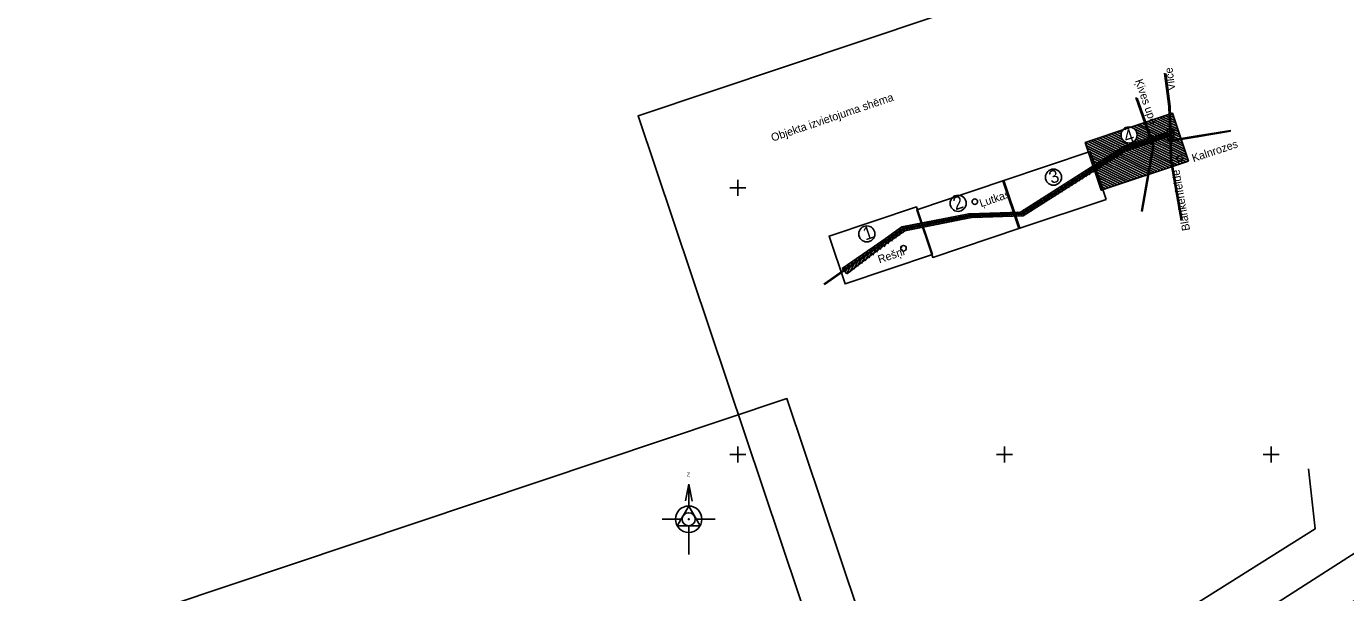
# Model space of a CAD drawing. Extents: x 469981 to 472086, y 246785 to 247785.
# Drawn here: x 471366.7 to 471613.9, y 247524.1 to 247630.3 of the extents above; entities that cross this region are included whole.
import ezdxf

# ---------------------------------------------------------------- set-up
doc = ezdxf.new("R2010")
doc.units = 0
for name, color, linetype in [('DREN_VADP_####_####_#', 7, 'Continuous'), ('GEOD_ELEM_####_####_#', 7, 'Continuous'), ('RAMI_PLAN_####_TKST_#', 7, 'Continuous'), ('RAMI_UZMR_####_####_#', 7, 'Continuous'), ('RELJ_NOGA_####_####_#', 7, 'Continuous'), ('RELJ_NOGL_####_####_#', 7, 'Continuous')]:
    doc.layers.add(name, color=color, linetype=linetype)

msp = doc.modelspace()

# ---------------------------------------------------------------- linework, layer by layer
at = {"layer": 'DREN_VADP_####_####_#'}
msp.add_lwpolyline([(471456.42, 247440.55), (471608.21, 247536.04), (471607, 247547.3)], dxfattribs=at)
at = {"layer": 'GEOD_ELEM_####_####_#'}
for p, q in [((471498.5, 247600), (471500, 247600)), ((471500, 247601.5), (471500, 247600)), ((471500, 247600), (471500, 247598.5)), ((471500, 247600), (471501.5, 247600)), ((471500, 247551.5), (471500, 247550)), ((471550, 247551.5), (471550, 247550)), ((471600, 247551.5), (471600, 247550)), ((471498.5, 247550), (471500, 247550)), ((471500, 247550), (471500, 247548.5)), ((471500, 247550), (471501.5, 247550)), ((471548.5, 247550), (471550, 247550)), ((471550, 247550), (471550, 247548.5)), ((471550, 247550), (471551.5, 247550)), ((471598.5, 247550), (471600, 247550)), ((471600, 247550), (471600, 247548.5)), ((471600, 247550), (471601.5, 247550))]:
    msp.add_line(p, q, dxfattribs=at)
at = {"layer": 'RAMI_PLAN_####_TKST_#'}
for p, q in [((471583.56, 247607.82), (471575.33, 247611.91)), ((471583.38, 247608.35), (471575.87, 247612.09)), ((471583.2, 247608.89), (471576.4, 247612.27)), ((471583.02, 247609.43), (471576.94, 247612.45)), ((471582.84, 247609.96), (471577.48, 247612.63)), ((471582.66, 247610.5), (471578.01, 247612.81)), ((471582.48, 247611.03), (471578.55, 247612.99)), ((471582.3, 247611.57), (471579.08, 247613.17)), ((471582.12, 247612.11), (471579.62, 247613.35)), ((471581.94, 247612.64), (471580.16, 247613.53)), ((471581.76, 247613.18), (471580.69, 247613.71)), ((471581.58, 247613.72), (471581.23, 247613.89)), ((471579.77, 247603.45), (471567.82, 247609.4)), ((471580.31, 247603.63), (471568.36, 247609.58)), ((471580.84, 247603.81), (471568.89, 247609.76)), ((471581.38, 247603.99), (471569.43, 247609.94)), ((471572.2, 247609.01), (471569.97, 247610.12)), ((471571.95, 247609.58), (471570.5, 247610.3)), ((471571.95, 247610.02), (471571.04, 247610.48)), ((471571.99, 247610.45), (471571.58, 247610.66)), ((471572.3, 247610.74), (471572.11, 247610.83)), ((471572.78, 247610.95), (471572.65, 247611.01)), ((471573.36, 247611.11), (471573.18, 247611.19)), ((471584.1, 247606.21), (471573.72, 247611.37)), ((471583.92, 247606.74), (471574.26, 247611.55)), ((471584.28, 247605.67), (471574.71, 247610.43)), ((471583.74, 247607.28), (471574.79, 247611.73)), ((471584.46, 247605.13), (471574.84, 247609.93)), ((471584.06, 247604.88), (471574.88, 247609.46)), ((471576.71, 247608.1), (471577.35, 247609.38)), ((471576.83, 247609.69), (471577.45, 247609.32)), ((471577.25, 247608.28), (471577.89, 247609.56)), ((471577.45, 247609.32), (471577.6, 247609.81)), ((471577.79, 247608.46), (471578.43, 247609.74)), ((471578.32, 247608.64), (471578.96, 247609.92)), ((471578.86, 247608.82), (471579.5, 247610.1)), ((471579.4, 247609), (471580.04, 247610.28)), ((471579.93, 247609.17), (471580.57, 247610.46)), ((471580.47, 247609.35), (471581.11, 247610.64)), ((471580.52, 247610.96), (471581.73, 247610.97)), ((471580.53, 247610.47), (471580.52, 247610.96)), ((471580.59, 247608.73), (471580.58, 247609.61)), ((471580.72, 247608.96), (471581.64, 247610.82)), ((471581.11, 247608.84), (471581.75, 247610.14)), ((471581.73, 247610.97), (471581.75, 247608.74)), ((471577.09, 247602.55), (471565.14, 247608.5)), ((471576.55, 247602.37), (471565.32, 247607.96)), ((471576.02, 247602.19), (471565.5, 247607.43)), ((471577.63, 247602.73), (471565.68, 247608.68)), ((471575.48, 247602.01), (471565.68, 247606.89)), ((471578.16, 247602.91), (471566.21, 247608.86)), ((471578.7, 247603.09), (471566.75, 247609.04)), ((471579.24, 247603.27), (471567.28, 247609.22)), ((471570.4, 247605.28), (471571.25, 247607)), ((471571.05, 247605.69), (471571.9, 247607.41)), ((471571.69, 247606.09), (471572.53, 247607.76)), ((471572.34, 247606.49), (471573.06, 247607.94)), ((471572.96, 247606.84), (471573.6, 247608.12)), ((471581.92, 247604.17), (471573.3, 247608.45)), ((471573.5, 247607.02), (471574.14, 247608.3)), ((471582.45, 247604.35), (471574.01, 247608.55)), ((471574.03, 247607.2), (471574.67, 247608.48)), ((471582.99, 247604.53), (471574.38, 247608.81)), ((471574.57, 247607.38), (471575.21, 247608.66)), ((471583.53, 247604.7), (471574.6, 247609.15)), ((471575.1, 247607.56), (471575.74, 247608.84)), ((471575.64, 247607.74), (471576.28, 247609.02)), ((471576.18, 247607.92), (471576.82, 247609.2)), ((471577.31, 247608.34), (471577.57, 247608.82)), ((471577.57, 247608.82), (471578.05, 247608.57)), ((471581.75, 247608.74), (471580.59, 247608.73)), ((471581.52, 247608.77), (471581.76, 247609.25)), ((471574.94, 247601.83), (471565.86, 247606.35)), ((471574.41, 247601.65), (471566.04, 247605.82)), ((471573.87, 247601.47), (471566.22, 247605.28)), ((471573.34, 247601.29), (471566.4, 247604.74)), ((471566.51, 247602.86), (471567.35, 247604.54)), ((471567.16, 247603.26), (471568, 247604.95)), ((471567.81, 247603.67), (471568.65, 247605.36)), ((471568.45, 247604.07), (471569.3, 247605.77)), ((471569.1, 247604.47), (471569.95, 247606.18)), ((471569.75, 247604.88), (471570.6, 247606.59)), ((471562.62, 247600.43), (471563.44, 247602.08)), ((471563.27, 247600.84), (471564.09, 247602.49)), ((471563.92, 247601.24), (471564.74, 247602.9)), ((471564.57, 247601.65), (471565.39, 247603.31)), ((471565.21, 247602.05), (471566.04, 247603.72)), ((471565.86, 247602.45), (471566.69, 247604.13)), ((471572.8, 247601.11), (471566.58, 247604.21)), ((471572.26, 247600.93), (471566.76, 247603.67)), ((471571.73, 247600.75), (471566.94, 247603.13)), ((471571.19, 247600.57), (471567.12, 247602.6)), ((471570.65, 247600.39), (471567.3, 247602.06)), ((471558.73, 247598.01), (471559.53, 247599.62)), ((471559.38, 247598.41), (471560.19, 247600.03)), ((471560.03, 247598.82), (471560.84, 247600.44)), ((471560.68, 247599.22), (471561.49, 247600.85)), ((471561.33, 247599.63), (471562.14, 247601.26)), ((471561.97, 247600.03), (471562.79, 247601.67)), ((471570.12, 247600.21), (471567.48, 247601.53)), ((471569.58, 247600.03), (471567.66, 247600.99)), ((471569.04, 247599.85), (471567.84, 247600.45)), ((471568.51, 247599.67), (471568.02, 247599.92)), ((471554.85, 247595.59), (471555.63, 247597.16)), ((471555.49, 247595.99), (471556.28, 247597.57)), ((471556.14, 247596.39), (471556.93, 247597.98)), ((471556.79, 247596.8), (471557.58, 247598.39)), ((471557.44, 247597.2), (471558.23, 247598.8)), ((471558.09, 247597.61), (471558.88, 247599.21)), ((471540.03, 247593.65), (471540.49, 247594.58)), ((471540.53, 247593.75), (471540.99, 247594.67)), ((471541.02, 247593.85), (471541.48, 247594.77)), ((471541.52, 247593.94), (471541.98, 247594.87)), ((471542.01, 247594.04), (471542.47, 247594.97)), ((471542.51, 247594.14), (471542.97, 247595.06)), ((471543, 247594.24), (471543.45, 247595.14)), ((471543.5, 247594.33), (471543.91, 247595.15)), ((471543.96, 247594.37), (471544.36, 247595.17)), ((471544.42, 247594.39), (471544.82, 247595.19)), ((471544.88, 247594.41), (471545.27, 247595.21)), ((471545.33, 247594.43), (471545.73, 247595.22)), ((471545.79, 247594.45), (471546.18, 247595.24)), ((471546.25, 247594.47), (471546.64, 247595.26)), ((471546.7, 247594.49), (471547.09, 247595.27)), ((471547.16, 247594.51), (471547.55, 247595.29)), ((471547.62, 247594.53), (471548, 247595.31)), ((471548.07, 247594.55), (471548.46, 247595.32)), ((471548.53, 247594.57), (471548.92, 247595.34)), ((471548.99, 247594.59), (471549.37, 247595.36)), ((471549.44, 247594.61), (471549.83, 247595.38)), ((471549.9, 247594.63), (471550.28, 247595.39)), ((471550.36, 247594.65), (471550.74, 247595.41)), ((471550.81, 247594.67), (471551.19, 247595.43)), ((471551.27, 247594.69), (471551.65, 247595.44)), ((471551.73, 247594.71), (471552.1, 247595.46)), ((471552.18, 247594.73), (471552.56, 247595.48)), ((471552.64, 247594.75), (471553.02, 247595.52)), ((471553.1, 247594.77), (471553.68, 247595.93)), ((471553.56, 247594.79), (471554.33, 247596.34)), ((471554.2, 247595.18), (471554.98, 247596.75)), ((471528.84, 247590.02), (471529.85, 247592.05)), ((471529.55, 247590.54), (471530.53, 247592.52)), ((471530.25, 247591.07), (471531.08, 247592.73)), ((471530.96, 247591.59), (471531.58, 247592.83)), ((471531.61, 247592), (471532.07, 247592.92)), ((471532.11, 247592.09), (471532.57, 247593.02)), ((471532.6, 247592.19), (471533.06, 247593.12)), ((471533.1, 247592.29), (471533.56, 247593.22)), ((471533.59, 247592.39), (471534.05, 247593.31)), ((471534.09, 247592.48), (471534.55, 247593.41)), ((471534.58, 247592.58), (471535.04, 247593.51)), ((471535.08, 247592.68), (471535.54, 247593.6)), ((471535.57, 247592.77), (471536.03, 247593.7)), ((471536.07, 247592.87), (471536.53, 247593.8)), ((471536.56, 247592.97), (471537.02, 247593.9)), ((471537.06, 247593.07), (471537.52, 247593.99)), ((471537.55, 247593.16), (471538.02, 247594.09)), ((471538.05, 247593.26), (471538.51, 247594.19)), ((471538.54, 247593.36), (471539.01, 247594.29)), ((471539.04, 247593.46), (471539.5, 247594.38)), ((471539.54, 247593.55), (471540, 247594.48)), ((471525.3, 247587.39), (471526.42, 247589.66)), ((471526.01, 247587.92), (471527.11, 247590.14)), ((471526.71, 247588.44), (471527.79, 247590.61)), ((471527.42, 247588.97), (471528.48, 247591.09)), ((471528.13, 247589.49), (471529.16, 247591.57)), ((471521.76, 247584.77), (471523, 247587.27)), ((471522.47, 247585.3), (471523.69, 247587.75)), ((471523.17, 247585.82), (471524.37, 247588.23)), ((471523.88, 247586.35), (471525.06, 247588.7)), ((471524.59, 247586.87), (471525.74, 247589.18)), ((471519.58, 247584.88), (471520.47, 247583.89)), ((471519.87, 247584.56), (471520.26, 247585.36)), ((471520.15, 247584.25), (471520.95, 247585.84)), ((471520.44, 247583.93), (471521.63, 247586.32)), ((471521.05, 247584.25), (471522.32, 247586.79)), ((471490.19, 247541.3), (471490.81, 247544.46)), ((471490.81, 247544.46), (471491.44, 247541.26)), ((471490.81, 247544.46), (471490.81, 247540.34)), ((471490.81, 247540.34), (471488.67, 247536.63)), ((471490.81, 247541.16), (471490.81, 247541)), ((471490.81, 247541), (471490.81, 247541.16)), ((471490.81, 247541.16), (471490.81, 247541)), ((471490.81, 247540.34), (471492.95, 247536.63)), ((471489.38, 247537.86), (471485.86, 247537.86)), ((471495.76, 247537.86), (471492.23, 247537.86)), ((471492.95, 247536.63), (471488.67, 247536.63)), ((471490.81, 247536.63), (471490.81, 247531.26))]:
    msp.add_line(p, q, dxfattribs=at)
for points in [[(472086.15, 247505.1), (471575.09, 247333.79), (471481.34, 247613.5), (471992.39, 247784.8)], [(471584.49, 247605.03), (471568.14, 247599.55), (471565.14, 247608.5), (471581.49, 247613.98)], [(471569.03, 247597.85), (471552.68, 247592.37), (471549.68, 247601.32), (471566.03, 247606.8)], [(471552.9, 247592.44), (471536.55, 247586.96), (471533.55, 247595.91), (471549.9, 247601.39)], [(471536.49, 247587.48), (471520.13, 247582), (471517.13, 247590.95), (471533.49, 247596.43)], [(471602.97, 247280.79), (471091.91, 247109.48), (470998.16, 247389.19), (471509.21, 247560.49)]]:
    msp.add_lwpolyline(points, close=True, dxfattribs=at)
for points in [[(471579.99, 247621.51), (471580.81, 247615.25), (471580.96, 247610.26)], [(471580.22, 247621.46), (471581.04, 247615.27), (471581.22, 247608.92)], [(471577.26, 247609.45), (471574.64, 247616.93)], [(471577.46, 247609.41), (471574.88, 247616.81)], [(471580.96, 247610.26), (471572.5, 247607.43), (471553.26, 247595.19), (471547.54, 247595), (471543.58, 247594.87), (471531.05, 247592.42), (471527.43, 247589.88), (471516.12, 247581.97)], [(471580.97, 247610.11), (471572.57, 247607.29), (471553.3, 247595.04), (471547.54, 247594.85), (471543.59, 247594.71), (471531.11, 247592.27), (471527.52, 247589.76), (471516.29, 247581.9)], [(471580.53, 247610.47), (471572.25, 247607.69), (471553.01, 247595.45), (471547.28, 247595.26), (471543.32, 247595.13), (471530.79, 247592.68), (471527.18, 247590.15), (471519.58, 247584.88)], [(471580.58, 247609.61), (471572.76, 247606.98), (471553.51, 247594.74), (471547.79, 247594.55), (471543.83, 247594.42), (471531.3, 247591.97), (471527.68, 247589.44), (471520.47, 247583.89)], [(471580.97, 247610.11), (471581.11, 247605.29), (471583.11, 247593.88)], [(471592.43, 247610.79), (471586.1, 247609.73), (471581.22, 247608.92)], [(471592.33, 247610.61), (471586.12, 247609.57), (471581.23, 247608.76)], [(471575.65, 247595.61), (471577.81, 247607.87), (471577.51, 247608.74)], [(471575.83, 247595.58), (471578, 247607.88), (471577.69, 247608.77)], [(471581.23, 247608.76), (471581.33, 247605.31), (471583.33, 247593.92)]]:
    msp.add_lwpolyline(points, dxfattribs=at)
for centre, radius in [((471573.35, 247609.92), 1.51), ((471582.83, 247605.5), 0.518), ((471559.18, 247602), 1.51), ((471541.31, 247597.11), 1.51), ((471544.45, 247597.42), 0.518), ((471524.2, 247591.37), 1.51), ((471531.07, 247588.68), 0.518), ((471490.81, 247537.86), 1.23), ((471490.81, 247537.86), 0.0872)]:
    msp.add_circle(centre, radius, dxfattribs=at)
for start, end in [(90, 270), (270, 90)]:
    msp.add_arc((471490.81, 247537.86), 2.48, start, end, dxfattribs=at)
at = {"layer": 'RAMI_UZMR_####_####_#'}
msp.add_lwpolyline([(471355.9, 247363.1), (471457.4, 247429.3), (471524.25, 247472.9), (471743.7, 247613.61), (471760.56, 247620.64), (471763.72, 247625.03), (471767.05, 247626.61), (471778.29, 247625.91), (471806.56, 247631.53), (471842.31, 247641.2)], dxfattribs=at)
at = {"layer": 'RELJ_NOGA_####_####_#'}
for points in [[(471341.93, 247360.74), (471344.51, 247356.26), (471349.95, 247353.75), (471355.9, 247354.99), (471376.69, 247368.01), (471396.06, 247380.32), (471444.05, 247411.05), (471471.48, 247428.43), (471497.59, 247445.1), (471529.06, 247465.66), (471552.02, 247480.39), (471579.85, 247498.34), (471608.29, 247516.96), (471640.01, 247537.43), (471663.53, 247552.84), (471700.31, 247577.15), (471731.58, 247597), (471755.89, 247610.64), (471758.96, 247612.21)], [(471398.63, 247372.11), (471402.43, 247374.78), (471425.59, 247389.13), (471450.06, 247404.81), (471474.14, 247419.97), (471503.22, 247438.68), (471533.57, 247458.24), (471556.87, 247473.39), (471582.76, 247490.01), (471614.04, 247510.51), (471643.17, 247529.24), (471669.12, 247546.6), (471690.76, 247560.62), (471694.71, 247563.16)]]:
    msp.add_spline(points, degree=3, dxfattribs=at)
at = {"layer": 'RELJ_NOGL_####_####_#'}
for points in [[(471342.51, 247361.02), (471345.4, 247356.89), (471350.22, 247354.86), (471355.25, 247356.42), (471376.01, 247368.36), (471395.6, 247380.99), (471443.66, 247411.57), (471471.28, 247429.25), (471497.37, 247445.87), (471528.27, 247466.83), (471551.61, 247481.24), (471579.42, 247499.1), (471607.69, 247517.41), (471639.59, 247538.32), (471662.84, 247553.56), (471699.58, 247577.98), (471731.35, 247598.06), (471755.71, 247611.43), (471758.27, 247612.73)], [(471399.82, 247371.52), (471403.25, 247373.92), (471426.14, 247388.27), (471450.97, 247403.91), (471474.46, 247419.14), (471503.7, 247437.9), (471533.87, 247457.48), (471557.48, 247472.58), (471583.18, 247489), (471614.92, 247509.52), (471643.61, 247528.29), (471669.95, 247545.7), (471691.54, 247559.7), (471695.15, 247562.05)]]:
    msp.add_spline(points, degree=3, dxfattribs=at)

# ---------------------------------------------------------------- texts
at = {"layer": 'RAMI_PLAN_####_TKST_#'}
for s, height, rotation, p in [('Vilce', 1.5, 97.4902, (471582.03, 247618.35)), ('Ķives upe', 1.5, 289.2796, (471574.42, 247620.09)), ('Objekta izvietojuma shēma', 1.5, 18.7527, (471506.54, 247608.66)), ('4', 2.4, 18.5312, (471572.82, 247608.32)), ('Kalnrozes', 1.5, 18.5312, (471585.42, 247604.81)), ('3', 2.4, 18.5312, (471558.79, 247600.72)), ('Blankenfelde', 1.5, 99.9444, (471584.79, 247592.08)), ('2', 2.4, 18.5312, (471540.83, 247595.78)), ('Ļutkas', 1.5, 18.5312, (471545.6, 247596.36)), ('1', 2.4, 18.5312, (471523.94, 247590.12)), ('Rešņi', 1.5, 18.5312, (471526.56, 247585.83))]:
    msp.add_text(s, height=height, rotation=rotation, dxfattribs=at).set_placement(p)
msp.add_text('Z', height=0.75, dxfattribs=at).set_placement((471490.45, 247545.9))

doc.saveas('drawing.dxf')
